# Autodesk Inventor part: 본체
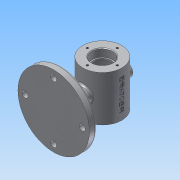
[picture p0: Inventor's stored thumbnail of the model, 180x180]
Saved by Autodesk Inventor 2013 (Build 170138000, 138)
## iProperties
Created: 2018-12
Part Number: 본체
Material: 알루미늄 6061
Document SubType Name: Modeling
Designer: Administrator
Mass: 687.613 g
Surface Area: 555.755 cm^2
Volume: 253.732 cm^3
Density: 2.71 g/cm^3
Author: Administrator
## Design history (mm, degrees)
sketch "스케치1"
  geometry: C1 r 30 at (0, 0); 1 further point
  constraints: 1 centre point, 1 coincident
  dimensions: "d0" = 60 diameter of C1
extrude "돌출1" new body sketch "스케치1" distance "d1" = 35; taper "d2" = 0 deg
hole "구멍1" diameter "d5" = 28; stored, may be unused: countersink angle "d9" = 90 deg, drill point angle "d11" = 0 deg; dims "d3" = 10, "d4" = 10, "d6" = 6, "d7" = 32, "d8" = 12, "d10" = 15
hole "구멍2" diameter "d14" = 50; stored, may be unused: countersink angle "d18" = 90 deg, drill point angle "d20" = 0 deg; dims "d12" = 10, "d13" = 10, "d15" = 6, "d16" = 32, "d17" = 12, "d19" = 20
sketch "스케치2"
  geometry: C1 r 16 at (0, 0) reference; 1 further point
  constraints: 1 vertical alignment
  dimensions: "d21" = 23 distance of C1.centre point (0, 23)
hole "구멍3" sketch "스케치2" at (0, 23) diameter "d22" = 3.242; stored, may be unused: countersink angle "d26" = 90 deg, drill point angle "d28" = 118 deg; dims "d23" = 8, "d24" = 32, "d25" = 12, "d27" = 10
chamfer "모따기1" distance "d32" = 1; stored, may be unused: second distance "d33" = 2, angle "d34" = 45 deg
fillet "모깎기1" dims "d35" = 3
node "작업 평면1"
sketch "스케치3"
  geometry: C1 r 55 at (0, 0); 1 further point
  constraints: 1 centre point, 1 coincident
  dimensions: "d37" = 110 diameter of C1
extrude "돌출2" join sketch "스케치3" distance "d38" = 11; taper "d39" = 0 deg
sketch "스케치4"
  geometry: C1 r 55 at (0, 0) reference; C2 r 55 at (0, 0) reference
extrude "돌출3" join sketch "스케치4" distance "d40" = 15; taper "d41" = -75 deg
sketch "스케치5"
  geometry: C1 r 55 at (0, 0) reference; C2 r 12 at (0, 0)
  constraints: 1 centre point, 1 coincident
  dimensions: "d42" = 24 diameter of C2
extrude "돌출4" join sketch "스케치5" stored distance "d43" = 15; taper "d44" = 0 deg
sketch "스케치6"
  geometry: C1 r 55 at (0, 0) reference; 1 further point
  constraints: 1 vertical alignment
  dimensions: "d45" = 44 distance of C1.centre point (0, 44)
hole "구멍4" sketch "스케치6" at (0, 44) diameter "d46" = 9; stored, may be unused: countersink angle "d50" = 90 deg, drill point angle "d52" = 0 deg; dims "d47" = 8, "d48" = 32, "d49" = 12, "d51" = 10
hole "구멍5" diameter "d55" = 14; stored, may be unused: countersink angle "d59" = 90 deg, drill point angle "d61" = 118 deg; dims "d53" = 10, "d54" = 10, "d56" = 8, "d57" = 32, "d58" = 12, "d60" = 10
node "작업 평면2"
sketch "스케치7"
  geometry: L1 (30, -35)-(-30, -35) reference; C1 r 10 at (0, 0); 1 further point
  constraints: 1 centre point, 1 coincident
  dimensions: "d66" = 20 diameter of C1; "d67" = 35 distance from line of C1.centre L1
extrude "돌출5" join sketch "스케치7" stored distance "d68" = 15; taper "d69" = 0 deg
hole "구멍6" diameter "d72" = 10; stored, may be unused: countersink angle "d76" = 90 deg, drill point angle "d78" = 0 deg; dims "d70" = 10, "d71" = 10, "d73" = 8, "d74" = 32, "d75" = 12, "d77" = 10
fillet "모깎기2" dims "d79" = 3
chamfer "모따기2" distance "d80" = 1; stored, may be unused: second distance "d81" = 2, angle "d82" = 45 deg
node "작업 평면3"
sketch "스케치8"
  geometry: L1 (30, 35)-(-30, 35) reference; L2 (30, -35)-(30, 35) reference; 2 further points
  constraints: 1 other
  dimensions: "d84" = 35 distance from line of point (0, 0) L1; "d85" = 30 distance from line of L2 point (0, 0)
feature "엠보싱1" sketch "스케치8" dims "d86" = 0.5, "d87" = 0
fillet "모깎기3" dims "d88" = 0.3
node "솔리드1"
pattern_circular "원형 패턴1" dims angle "d30" = 360 deg
mirror "대칭1"
pattern_circular "원형 패턴2" dims angle "d63" = 360 deg
node "투영된 루프1"
other parameters: "d36" = -75, "d65" = -112, "d83" = 64
